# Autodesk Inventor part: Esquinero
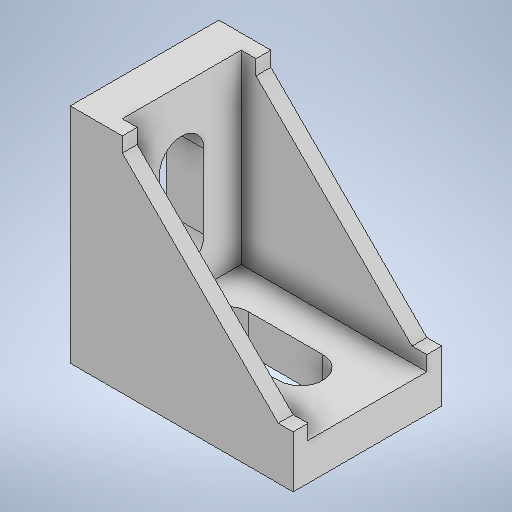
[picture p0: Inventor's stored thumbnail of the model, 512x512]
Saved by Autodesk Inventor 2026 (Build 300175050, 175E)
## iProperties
Created: 2025-06
Part Number: Esquinero
Material: Genérico
Document SubType Name: Modeling
Designer: piero
Density: 1 g/cm^3
Appearance: Valor por defecto
Author: piero
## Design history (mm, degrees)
sketch "Boceto1"
  geometry: L1 (0, 0)-(30, 0); L2 (30, 0)-(30, -20); L3 (30, -20)-(0, -20); L4 (0, -20)-(0, 0); L5 (21, -10)-(11, -10); L6 (21, -7)-(11, -7); L7 (11, -13)-(21, -13); A1 r 3 centre (21, -10) between (21, -13) and (21, -7); A2 r 3 centre (11, -10) between (11, -7) and (11, -13); 5 further points
  constraints: 16 end point, 6 point on circle, 4 tangent, 3 midpoint, 3 parallel, 2 centre point, 2 horizontal, 1 perpendicular
  dimensions: "d0" = 30 distance of L2.end L3.end; "d1" = 20 distance of L1.end L2.end; "d2" = 10 distance of L5.start L5.end; "d3" = 6 diameter of A2; "d4" = 6 distance of point (24, -10) point (30, -10)
extrude "Extrusión1" new body sketch "Boceto1" distance "d6" = 5; taper "d7" = 0 deg
sketch "Boceto2"
  geometry: L1 (0, 0)-(20, 0) reference; L2 (0, 0)-(20, 0); L3 (20, 0)-(20, 5); L4 (20, 5)-(0, 5); L5 (0, 5)-(0, 0); 1 further point
  constraints: 8 end point, 2 parallel, 1 horizontal, 1 perpendicular
  dimensions: "d8" = 20 distance of L4.end L3.end; "d9" = 5 distance of L3.end L2.end
extrude "Extrusión2" join sketch "Boceto2" distance "d10" = 25; taper "d11" = 0 deg
sketch "Boceto3"
  geometry: L1 (6, 10)-(16, 10); L2 (6, 7)-(16, 7); L3 (16, 13)-(6, 13); L4 (25, 20)-(25, 0) reference; L5 (0, 0)-(25, 0) reference; A1 r 3 centre (6, 10) between (6, 13) and (6, 7); A2 r 3 centre (16, 10) between (16, 7) and (16, 13); 4 further points
  constraints: 8 end point, 5 point on circle, 4 tangent, 2 centre point, 2 midpoint, 1 horizontal, 1 parallel
  dimensions: "d12" = 10 distance of L1.start L1.end; "d13" = 6 diameter of A2; "d14" = 6 distance of point (25, 10) point (19, 10); "d15" = 10 distance from line of L5 point (11, 10)
extrude "Extrusión3" cut sketch "Boceto3" distance "d16" = 5; taper "d17" = 0 deg
sketch "Boceto4"
  geometry: L1 (5, 30)-(5, 5) reference; L2 (5, 5)-(30, 5) reference; L3 (5, 5)-(5, 28); L4 (5, 30)-(7, 30); L5 (7, 30)-(7, 28); L6 (30, 5)-(30, 7); L7 (30, 7)-(28, 7); L8 (28, 7)-(7, 28); 2 further points
  constraints: 12 end point, 3 perpendicular, 2 point on line, 1 horizontal, 1 vertical
  dimensions: "d18" = 2 distance of L3.end L1.start; "d19" = 2 distance of point (28, 5) L2.end; "d22" = 2 distance of L2.end L6.end
extrude "Extrusión4" join sketch "Boceto4" distance "d20" = 2; taper "d21" = 0 deg
sketch "Boceto5"
  geometry: L1 (-30, 0)-(-30, 5) reference; L2 (-30, 0)-(-30, 7) reference; L3 (-30, 5)-(-30, 7); L4 (-30, 7)-(-28, 7); L5 (-7, 30)-(-7, 28) reference; L6 (-28, 7)-(-7, 28); L7 (-7, 28)-(-7, 30); L8 (-7, 30)-(-5, 30); L9 (-5, 30)-(-5, 5); L10 (-5, 5)-(-30, 5); 1 further point
  constraints: 14 end point, 4 perpendicular, 1 collinear, 1 point on line, 1 vertical
  dimensions: "d23" = 2 distance of L2.end L4.end
extrude "Extrusión5" join sketch "Boceto5" distance "d24" = 2; taper "d25" = 0 deg
node "Sólido1"
